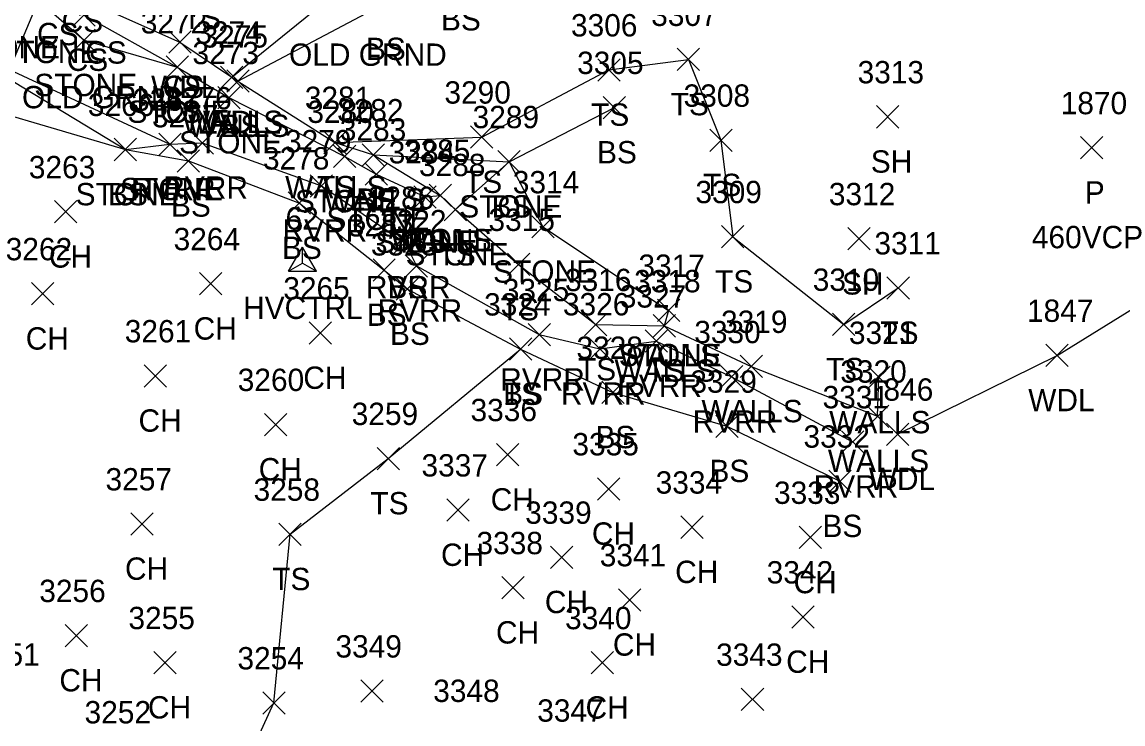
# Model space of a CAD drawing. Extents: x 462930 to 463548, y 29607 to 30453.
# Drawn here: x 463356.77 to 463386.81, y 30121.35 to 30140.5 of the extents above; entities that cross this region are included whole.
import ezdxf

# ---------------------------------------------------------------- set-up
doc = ezdxf.new("R2010")
doc.units = 0
for name, color, linetype in [('C_A', 7, 'Continuous'), ('C_I', 7, 'Continuous'), ('CPSM', 7, 'Continuous'), ('D_A', 7, 'Continuous'), ('D_C', 7, 'Continuous'), ('D_I', 7, 'Continuous'), ('D_TIC', 7, 'Continuous'), ('L_A', 7, 'Continuous'), ('L_C', 7, 'Continuous'), ('L_I', 7, 'Continuous'), ('L_TIC', 7, 'Continuous'), ('LASF', 7, 'Continuous'), ('LAWA', 7, 'Continuous'), ('LAWE', 7, 'Continuous'), ('LELB', 7, 'Continuous'), ('LWS', 7, 'Continuous'), ('UW', 7, 'Continuous')]:
    doc.layers.add(name, color=color, linetype=linetype)

msp = doc.modelspace()

# ---------------------------------------------------------------- linework, layer by layer
at = {"layer": 'CPSM'}
for p, q in [((463364.036, 30133.701), (463364.417, 30134.361)), ((463364.798, 30133.701), (463364.417, 30134.361)), ((463364.417, 30133.921), (463364.417, 30134.361)), ((463364.036, 30133.701), (463364.417, 30133.921)), ((463364.036, 30133.701), (463364.798, 30133.701)), ((463364.417, 30133.921), (463364.417, 30133.921)), ((463364.417, 30133.921), (463364.798, 30133.701))]:
    msp.add_line(p, q, dxfattribs=at)
at = {"layer": 'D_TIC'}
for points in [[(463385.651, 30136.765), (463386.261, 30137.375)], [(463386.261, 30136.765), (463385.651, 30137.375)]]:
    msp.add_lwpolyline(points, dxfattribs=at)
at = {"layer": 'L_TIC'}
for points in [[(463358.156, 30140.385), (463358.766, 30140.994)], [(463358.766, 30140.385), (463358.156, 30140.994)], [(463358.155, 30139.697), (463358.765, 30140.306)], [(463358.765, 30139.697), (463358.155, 30140.306)], [(463360.77, 30139.646), (463361.38, 30140.256)], [(463361.38, 30139.646), (463360.77, 30140.256)], [(463360.77, 30139.646), (463361.38, 30140.256)], [(463361.38, 30139.646), (463360.77, 30140.256)], [(463374.647, 30139.174), (463375.257, 30139.784)], [(463375.257, 30139.174), (463374.647, 30139.784)], [(463360.696, 30138.968), (463361.306, 30139.578)], [(463361.306, 30138.968), (463360.696, 30139.578)], [(463360.696, 30138.968), (463361.306, 30139.578)], [(463361.306, 30138.968), (463360.696, 30139.578)], [(463372.476, 30138.888), (463373.086, 30139.498)], [(463373.086, 30138.888), (463372.476, 30139.498)], [(463362.185, 30138.69), (463362.794, 30139.3)], [(463362.794, 30138.69), (463362.185, 30139.3)], [(463362.185, 30138.69), (463362.794, 30139.3)], [(463362.794, 30138.69), (463362.185, 30139.3)], [(463362.353, 30138.584), (463362.962, 30139.193)], [(463362.962, 30138.584), (463362.353, 30139.193)], [(463362.353, 30138.584), (463362.962, 30139.193)], [(463362.962, 30138.584), (463362.353, 30139.193)], [(463362.106, 30138.132), (463362.715, 30138.742)], [(463362.715, 30138.132), (463362.106, 30138.742)], [(463372.627, 30137.862), (463373.237, 30138.472)], [(463373.237, 30137.862), (463372.627, 30138.472)], [(463380.083, 30137.608), (463380.692, 30138.218)], [(463380.692, 30137.608), (463380.083, 30138.218)], [(463369.008, 30137.055), (463369.618, 30137.664)], [(463369.618, 30137.055), (463369.008, 30137.664)], [(463359.282, 30136.717), (463359.892, 30137.327)], [(463359.892, 30136.717), (463359.282, 30137.327)], [(463359.282, 30136.717), (463359.892, 30137.327)], [(463359.892, 30136.717), (463359.282, 30137.327)], [(463360.497, 30136.858), (463361.107, 30137.468)], [(463361.107, 30136.858), (463360.497, 30137.468)], [(463360.497, 30136.858), (463361.107, 30137.468)], [(463361.107, 30136.858), (463360.497, 30137.468)], [(463361.38, 30136.897), (463361.99, 30137.507)], [(463361.99, 30136.897), (463361.38, 30137.507)], [(463364.999, 30136.908), (463365.609, 30137.518)], [(463365.609, 30136.908), (463364.999, 30137.518)], [(463364.999, 30136.908), (463365.609, 30137.518)], [(463365.609, 30136.908), (463364.999, 30137.518)], [(463375.531, 30136.969), (463376.141, 30137.578)], [(463376.141, 30136.969), (463375.531, 30137.578)], [(463361.001, 30136.407), (463361.611, 30137.017)], [(463361.611, 30136.407), (463361.001, 30137.017)], [(463365.267, 30136.528), (463365.877, 30137.138)], [(463365.877, 30136.528), (463365.267, 30137.138)], [(463366.052, 30136.569), (463366.662, 30137.179)], [(463366.662, 30136.569), (463366.052, 30137.179)], [(463366.052, 30136.569), (463366.662, 30137.179)], [(463366.662, 30136.569), (463366.052, 30137.179)], [(463369.753, 30136.384), (463370.362, 30136.994)], [(463370.362, 30136.384), (463369.753, 30136.994)], [(463369.753, 30136.384), (463370.362, 30136.994)], [(463370.362, 30136.384), (463369.753, 30136.994)], [(463366.127, 30136.044), (463366.737, 30136.653)], [(463366.737, 30136.044), (463366.127, 30136.653)], [(463364.633, 30135.725), (463365.243, 30136.334)], [(463365.243, 30135.725), (463364.633, 30136.334)], [(463364.03, 30135.255), (463364.639, 30135.865)], [(463364.639, 30135.255), (463364.03, 30135.865)], [(463367.461, 30135.423), (463368.07, 30136.033)], [(463368.07, 30135.423), (463367.461, 30136.033)], [(463367.461, 30135.423), (463368.07, 30136.033)], [(463368.07, 30135.423), (463367.461, 30136.033)], [(463367.875, 30135.464), (463368.485, 30136.074)], [(463368.485, 30135.464), (463367.875, 30136.074)], [(463367.875, 30135.464), (463368.485, 30136.074)], [(463368.485, 30135.464), (463367.875, 30136.074)], [(463357.656, 30135.017), (463358.265, 30135.627)], [(463358.265, 30135.017), (463357.656, 30135.627)], [(463368.287, 30135.076), (463368.897, 30135.685)], [(463368.897, 30135.076), (463368.287, 30135.685)], [(463368.287, 30135.076), (463368.897, 30135.685)], [(463368.897, 30135.076), (463368.287, 30135.685)], [(463370.674, 30134.607), (463371.283, 30135.216)], [(463371.283, 30134.607), (463370.674, 30135.216)], [(463375.857, 30134.338), (463376.467, 30134.948)], [(463376.467, 30134.338), (463375.857, 30134.948)], [(463379.299, 30134.282), (463379.909, 30134.892)], [(463379.909, 30134.282), (463379.299, 30134.892)], [(463366.908, 30134.18), (463367.518, 30134.79)], [(463367.518, 30134.18), (463366.908, 30134.79)], [(463366.908, 30134.18), (463367.518, 30134.79)], [(463367.518, 30134.18), (463366.908, 30134.79)], [(463366.344, 30133.428), (463366.953, 30134.038)], [(463366.953, 30133.428), (463366.344, 30134.038)], [(463367.225, 30133.542), (463367.834, 30134.151)], [(463367.834, 30133.542), (463367.225, 30134.151)], [(463370.01, 30133.58), (463370.62, 30134.189)], [(463370.62, 30133.58), (463370.01, 30134.189)], [(463357.025, 30132.78), (463357.634, 30133.389)], [(463357.634, 30132.78), (463357.025, 30133.389)], [(463361.606, 30133.054), (463362.216, 30133.663)], [(463362.216, 30133.054), (463361.606, 30133.663)], [(463366.976, 30132.908), (463367.586, 30133.518)], [(463367.586, 30132.908), (463366.976, 30133.518)], [(463380.369, 30132.938), (463380.979, 30133.548)], [(463380.979, 30132.938), (463380.369, 30133.548)], [(463374.103, 30132.326), (463374.712, 30132.936)], [(463374.712, 30132.326), (463374.103, 30132.936)], [(463374.103, 30132.326), (463374.712, 30132.936)], [(463374.712, 30132.326), (463374.103, 30132.936)], [(463372.116, 30131.939), (463372.726, 30132.548)], [(463372.726, 30131.939), (463372.116, 30132.548)], [(463373.986, 30131.905), (463374.595, 30132.515)], [(463374.595, 30131.905), (463373.986, 30132.515)], [(463373.986, 30131.905), (463374.595, 30132.515)], [(463374.595, 30131.905), (463373.986, 30132.515)], [(463378.886, 30131.945), (463379.495, 30132.554)], [(463379.495, 30131.945), (463378.886, 30132.554)], [(463364.599, 30131.709), (463365.208, 30132.319)], [(463365.208, 30131.709), (463364.599, 30132.319)], [(463370.574, 30131.664), (463371.183, 30132.273)], [(463371.183, 30131.664), (463370.574, 30132.273)], [(463372.231, 30131.276), (463372.841, 30131.886)], [(463372.841, 30131.276), (463372.231, 30131.886)], [(463373.767, 30131.489), (463374.377, 30132.099)], [(463374.377, 30131.489), (463373.767, 30132.099)], [(463370.065, 30131.272), (463370.674, 30131.882)], [(463370.674, 30131.272), (463370.065, 30131.882)], [(463370.065, 30131.272), (463370.674, 30131.882)], [(463370.674, 30131.272), (463370.065, 30131.882)], [(463384.705, 30131.099), (463385.315, 30131.709)], [(463385.315, 30131.099), (463384.705, 30131.709)], [(463376.359, 30130.797), (463376.969, 30131.406)], [(463376.969, 30130.797), (463376.359, 30131.406)], [(463360.101, 30130.54), (463360.71, 30131.15)], [(463360.71, 30130.54), (463360.101, 30131.15)], [(463375.825, 30130.517), (463376.435, 30131.126)], [(463376.435, 30130.517), (463375.825, 30131.126)], [(463379.846, 30130.496), (463380.456, 30131.105)], [(463380.456, 30130.496), (463379.846, 30131.105)], [(463372.585, 30130.089), (463373.195, 30130.699)], [(463373.195, 30130.089), (463372.585, 30130.699)], [(463363.381, 30129.212), (463363.991, 30129.821)], [(463363.991, 30129.212), (463363.381, 30129.821)], [(463379.81, 30129.44), (463380.419, 30130.049)], [(463380.419, 30129.44), (463379.81, 30130.049)], [(463375.695, 30129.165), (463376.305, 30129.775)], [(463376.305, 30129.165), (463375.695, 30129.775)], [(463380.353, 30128.948), (463380.963, 30129.558)], [(463380.963, 30128.948), (463380.353, 30129.558)], [(463379.127, 30128.74), (463379.737, 30129.349)], [(463379.737, 30128.74), (463379.127, 30129.349)], [(463366.453, 30128.284), (463367.063, 30128.894)], [(463367.063, 30128.284), (463366.453, 30128.894)], [(463369.711, 30128.389), (463370.32, 30128.998)], [(463370.32, 30128.389), (463369.711, 30128.998)], [(463372.473, 30127.456), (463373.082, 30128.066)], [(463373.082, 30127.456), (463372.473, 30128.066)], [(463378.78, 30127.666), (463379.389, 30128.275)], [(463379.389, 30127.666), (463378.78, 30128.275)], [(463368.356, 30126.878), (463368.966, 30127.488)], [(463368.966, 30126.878), (463368.356, 30127.488)], [(463359.733, 30126.499), (463360.343, 30127.109)], [(463360.343, 30126.499), (463359.733, 30127.109)], [(463363.774, 30126.217), (463364.384, 30126.826)], [(463364.384, 30126.217), (463363.774, 30126.826)], [(463374.745, 30126.411), (463375.355, 30127.021)], [(463375.355, 30126.411), (463374.745, 30127.021)], [(463377.975, 30126.132), (463378.585, 30126.742)], [(463378.585, 30126.132), (463377.975, 30126.742)], [(463371.189, 30125.589), (463371.798, 30126.199)], [(463371.798, 30125.589), (463371.189, 30126.199)], [(463369.856, 30124.759), (463370.465, 30125.368)], [(463370.465, 30124.759), (463369.856, 30125.368)], [(463373.046, 30124.428), (463373.656, 30125.037)], [(463373.656, 30124.428), (463373.046, 30125.037)], [(463377.774, 30123.96), (463378.384, 30124.57)], [(463378.384, 30123.96), (463377.774, 30124.57)], [(463357.942, 30123.453), (463358.552, 30124.063)], [(463358.552, 30123.453), (463357.942, 30124.063)], [(463360.359, 30122.714), (463360.969, 30123.324)], [(463360.969, 30122.714), (463360.359, 30123.324)], [(463372.3, 30122.711), (463372.91, 30123.321)], [(463372.91, 30122.711), (463372.3, 30123.321)], [(463366.01, 30121.939), (463366.619, 30122.548)], [(463366.619, 30121.939), (463366.01, 30122.548)], [(463376.394, 30121.713), (463377.004, 30122.322)], [(463377.004, 30121.713), (463376.394, 30122.322)], [(463363.333, 30121.614), (463363.943, 30122.224)], [(463363.943, 30121.614), (463363.333, 30122.224)]]:
    msp.add_lwpolyline(points, dxfattribs=at)
at = {"layer": 'LASF'}
for points in [[(463335.666, 30151.825), (463334.307, 30149.365), (463333.551, 30148), (463337.382, 30145.968), (463341.269, 30144.863), (463346.266, 30143.58), (463350.176, 30142.23), (463354.589, 30140.054), (463359.587, 30137.022), (463360.802, 30137.163)], [(463335.666, 30151.825), (463339.994, 30150.186), (463344.731, 30148.092), (463345.991, 30147.14), (463346.905, 30145.251), (463349.408, 30144.305), (463351.788, 30143.206), (463354.335, 30142.295), (463356.35, 30141.031), (463357.426, 30140.903), (463358.46, 30140.002), (463361.001, 30139.273), (463362.41, 30138.437), (463365.572, 30136.833), (463366.432, 30136.349), (463367.765, 30135.728), (463368.18, 30135.769), (463368.592, 30135.381), (463370.057, 30136.689), (463370.978, 30134.911), (463374.408, 30132.631)]]:
    msp.add_lwpolyline(points, dxfattribs=at)
at = {"layer": 'LAWA'}
for points in [[(463380.658, 30129.253), (463385.01, 30131.404), (463390.048, 30134.524), (463393.052, 30140.479), (463397.05, 30150.402), (463401.541, 30159.789)], [(463361.075, 30139.951), (463362.489, 30138.995), (463366.254, 30142.049), (463368.112, 30145.132), (463368.96, 30147.708), (463370.031, 30148.832), (463372.15, 30149.242), (463373.697, 30150.393), (463375.482, 30151.895)]]:
    msp.add_lwpolyline(points, dxfattribs=at)
at = {"layer": 'LAWE'}
msp.add_lwpolyline([(463312.771, 30156.48), (463317.927, 30154.119), (463323.301, 30150.297), (463329.2, 30147.672), (463333.781, 30145.982), (463336.917, 30145.16), (463341.124, 30143.089), (463345.902, 30142.661), (463349.953, 30140.952), (463354.589, 30140.054), (463360.802, 30137.163), (463361.685, 30137.202), (463364.938, 30136.029), (463367.213, 30134.485), (463367.529, 30133.847), (463370.878, 30131.969), (463372.536, 30131.581), (463374.072, 30131.794), (463376.13, 30130.821), (463379.432, 30129.045)], dxfattribs=at)
at = {"layer": 'LELB'}
for points in [[(463311.51, 30154.564), (463317.305, 30152.12), (463328.108, 30145.648), (463332.48, 30143.532), (463335.24, 30142.565), (463339.678, 30141.183), (463343.544, 30141.846), (463345.752, 30141.37), (463349.534, 30139.719), (463354.026, 30138.661), (463359.587, 30137.022), (463361.306, 30136.712), (463364.334, 30135.56), (463366.649, 30133.733), (463367.281, 30133.213), (463370.369, 30131.577), (463372.89, 30130.394), (463376, 30129.47), (463379.084, 30127.97)], [(463362.657, 30138.888), (463366.626, 30140.987), (463368.673, 30141.794), (463369.614, 30144.668), (463372.764, 30146.82), (463375.23, 30148.304), (463377.492, 30152.624)], [(463338.725, 30147.014), (463341.902, 30146.288), (463346.905, 30145.251), (463349.39, 30146.891), (463350.92, 30147.048), (463352.297, 30147.355), (463353.139, 30145.924), (463354.358, 30144.307), (463355.85, 30144.681), (463357.539, 30144.184), (463357.985, 30144.223), (463357.945, 30143.102), (463357.652, 30141.391), (463358.461, 30140.69), (463361.001, 30139.273)], [(463357.985, 30144.223), (463358.976, 30143.588), (463358.67, 30142.627), (463358.321, 30141.75), (463358.966, 30140.889), (463361.075, 30139.951)], [(463365.304, 30137.213), (463369.313, 30137.36), (463372.781, 30139.193), (463374.952, 30139.479), (463375.836, 30137.274), (463376.162, 30134.643), (463379.19, 30132.249), (463380.674, 30133.243)], [(463366.357, 30136.874), (463370.057, 30136.689), (463372.932, 30138.167)], [(463367.765, 30135.728), (463367.213, 30134.485)], [(463368.592, 30135.381), (463370.315, 30133.884), (463372.421, 30132.243), (463374.291, 30132.21)], [(463357.518, 30115.65), (463362.332, 30119.061), (463363.638, 30121.919), (463364.079, 30126.521), (463366.758, 30128.589), (463370.369, 30131.577)]]:
    msp.add_lwpolyline(points, dxfattribs=at)
at = {"layer": 'LWS'}
for points in [[(463362.489, 30138.995), (463362.657, 30138.888), (463365.304, 30137.213), (463366.357, 30136.874), (463368.18, 30135.769)], [(463374.408, 30132.631), (463374.291, 30132.21), (463376.664, 30131.102), (463380.114, 30129.744), (463380.151, 30130.801)]]:
    msp.add_lwpolyline(points, dxfattribs=at)
at = {"layer": 'UW'}
msp.add_lwpolyline([(463344.573, 30111.096), (463359.121, 30145.596)], dxfattribs=at)

# ---------------------------------------------------------------- texts
at = {"layer": 'C_A'}
msp.add_text('HVCTRL', height=0.6096, dxfattribs=at).set_placement((463362.799, 30132.397))
at = {"layer": 'C_I'}
msp.add_text('62', height=0.6096, dxfattribs=at).set_placement((463363.956, 30134.835))
at = {"layer": 'D_A'}
msp.add_text('P', height=0.61, dxfattribs=at).set_placement((463385.766, 30135.546))
at = {"layer": 'D_C'}
msp.add_text('460VCP', height=0.6096, dxfattribs=at).set_placement((463384.322, 30134.327))
at = {"layer": 'D_I'}
msp.add_text('1870', height=0.6096, dxfattribs=at).set_placement((463385.109, 30137.984))
at = {"layer": 'L_A'}
for s, p in [('TS', (463361.158, 30140.307)), ('CS', (463357.846, 30140.226)), ('BS', (463368.198, 30140.27)), ('CS', (463357.176, 30139.867)), ('STONE', (463354.992, 30139.507)), ('STONE', (463356.068, 30139.379)), ('BS', (463366.151, 30139.463)), ('CS', (463357.986, 30139.166)), ('CS', (463358.491, 30139.365)), ('STONE', (463357.101, 30138.478)), ('WDL', (463360.288, 30138.427)), ('CS', (463360.6, 30138.427)), ('TS', (463374.467, 30137.955)), ('STONE', (463359.643, 30137.749)), ('CS', (463360.526, 30137.749)), ('TS', (463372.296, 30137.669)), ('WALLS', (463361.131, 30137.471)), ('WALLS', (463361.299, 30137.364)), ('WDL', (463361.702, 30137.471)), ('BS', (463362.182, 30137.364)), ('STONE', (463361.052, 30136.913)), ('BS', (463372.457, 30136.643)), ('SH', (463379.927, 30136.389)), ('TS', (463368.828, 30135.836)), ('STONE', (463358.229, 30135.498)), ('BS', (463359.112, 30135.498)), ('STONE', (463359.444, 30135.639)), ('RVRR', (463359.739, 30135.639)), ('RVRR', (463360.622, 30135.678)), ('WALLS', (463363.946, 30135.689)), ('TS', (463364.819, 30135.689)), ('TS', (463375.352, 30135.75)), ('BS', (463360.831, 30135.188)), ('STONE', (463364.214, 30135.309)), ('WALLS', (463364.999, 30135.35)), ('BS', (463365.882, 30135.35)), ('STONE', (463368.699, 30135.165)), ('BS', (463369.582, 30135.165)), ('STONE', (463365.073, 30134.825)), ('RVRR', (463363.875, 30134.505)), ('BS', (463363.859, 30134.036)), ('STONE', (463366.407, 30134.204)), ('WALLS', (463366.822, 30134.245)), ('STONE', (463366.822, 30134.245)), ('BS', (463367.29, 30134.204)), ('CH', (463357.5, 30133.798)), ('STONE', (463367.233, 30133.857)), ('TS', (463368.107, 30133.857)), ('STONE', (463369.62, 30133.387)), ('TS', (463375.677, 30133.119)), ('RVRR', (463366.15, 30132.961)), ('BS', (463366.738, 30132.961)), ('SH', (463379.143, 30133.063)), ('BS', (463366.173, 30132.209)), ('RVRR', (463366.466, 30132.323)), ('TS', (463369.83, 30132.36)), ('CH', (463361.45, 30131.834)), ('BS', (463366.806, 30131.689)), ('TS', (463380.189, 30131.719)), ('CH', (463356.869, 30131.561)), ('WALLS', (463373.049, 30131.107)), ('STONE', (463373.049, 30131.107)), ('TS', (463371.936, 30130.719)), ('WALLS', (463372.932, 30130.686)), ('TS', (463373.806, 30130.686)), ('TS', (463378.706, 30130.725)), ('CH', (463364.443, 30130.49)), ('RVRR', (463369.815, 30130.445)), ('RVRR', (463373.009, 30130.27)), ('TS', (463369.885, 30130.053)), ('BS', (463369.894, 30130.053)), ('RVRR', (463371.473, 30130.057)), ('WDL', (463384.223, 30129.88)), ('WALLS', (463375.306, 30129.578)), ('CH', (463359.945, 30129.321)), ('RVRR', (463375.067, 30129.297)), ('WALLS', (463378.792, 30129.277)), ('BS', (463372.415, 30128.87)), ('CH', (463363.225, 30127.993)), ('WALLS', (463378.756, 30128.22)), ('BS', (463375.525, 30127.946)), ('WDL', (463379.871, 30127.729)), ('RVRR', (463378.369, 30127.521)), ('TS', (463366.273, 30127.065)), ('CH', (463369.555, 30127.169)), ('CH', (463372.317, 30126.237)), ('BS', (463378.609, 30126.446)), ('CH', (463368.2, 30125.659)), ('CH', (463359.577, 30125.28)), ('TS', (463363.594, 30124.997)), ('CH', (463374.589, 30125.192)), ('CH', (463377.819, 30124.913)), ('CH', (463371.033, 30124.37)), ('CH', (463369.7, 30123.54)), ('CH', (463372.89, 30123.209)), ('CH', (463377.618, 30122.741)), ('CH', (463357.786, 30122.234)), ('CH', (463360.203, 30121.495)), ('CH', (463372.144, 30121.492))]:
    msp.add_text(s, height=0.6096, dxfattribs=at).set_placement(p)
at = {"layer": 'L_C'}
for p in [(463364.053, 30139.305), (463356.766, 30138.146)]:
    msp.add_text('OLD GRND', height=0.6096, dxfattribs=at).set_placement(p)
at = {"layer": 'L_I'}
for s, p in [('3307', (463373.935, 30140.393)), ('3272', (463360.007, 30140.188)), ('3272', (463360.007, 30140.188)), ('3306', (463371.746, 30140.107)), ('3274', (463361.496, 30139.909)), ('3274', (463361.496, 30139.909)), ('3275', (463361.664, 30139.803)), ('3275', (463361.664, 30139.803)), ('3273', (463361.417, 30139.351)), ('3305', (463371.914, 30139.082)), ('3313', (463379.567, 30138.827)), ('3290', (463368.293, 30138.274)), ('3308', (463374.819, 30138.188)), ('3266', (463358.562, 30137.936)), ('3266', (463358.562, 30137.936)), ('3267', (463359.794, 30138.077)), ('3267', (463359.794, 30138.077)), ('3276', (463360.675, 30138.116)), ('3281', (463364.483, 30138.127)), ('3281', (463364.483, 30138.127)), ('3277', (463360.312, 30137.626)), ('3280', (463364.552, 30137.747)), ('3282', (463365.364, 30137.788)), ('3282', (463365.364, 30137.788)), ('3289', (463369.061, 30137.603)), ('3289', (463369.061, 30137.603)), ('3283', (463365.438, 30137.263)), ('3279', (463363.942, 30136.944)), ('3285', (463367.186, 30136.684)), ('3285', (463367.186, 30136.684)), ('3278', (463363.341, 30136.475)), ('3284', (463366.772, 30136.642)), ('3284', (463366.772, 30136.642)), ('3263', (463356.952, 30136.236)), ('3288', (463367.598, 30136.295)), ('3288', (463367.598, 30136.295)), ('3314', (463370.158, 30135.826)), ('3309', (463375.142, 30135.557)), ('3312', (463378.783, 30135.501)), ('3286', (463366.202, 30135.399)), ('3286', (463366.202, 30135.399)), ('3287', (463365.655, 30134.648)), ('3322', (463366.536, 30134.761)), ('3315', (463369.494, 30134.799)), ('3264', (463360.903, 30134.273)), ('3262', (463356.321, 30133.999)), ('3323', (463366.287, 30134.128)), ('3311', (463380.026, 30134.158)), ('3317', (463373.587, 30133.546)), ('3317', (463373.587, 30133.546)), ('3316', (463371.583, 30133.158)), ('3318', (463373.47, 30133.125)), ('3318', (463373.47, 30133.125)), ('3310', (463378.343, 30133.164)), ('3265', (463363.896, 30132.929)), ('3325', (463369.885, 30132.883)), ('3324', (463369.376, 30132.491)), ('3324', (463369.376, 30132.491)), ('3326', (463371.526, 30132.495)), ('3327', (463373.078, 30132.708)), ('1847', (463384.189, 30132.318)), ('3319', (463375.841, 30132.016)), ('3261', (463359.57, 30131.759)), ('3330', (463375.11, 30131.736)), ('3321', (463379.33, 30131.715)), ('3328', (463371.896, 30131.308)), ('3260', (463362.652, 30130.431)), ('3329', (463375.004, 30130.384)), ('3320', (463379.094, 30130.659)), ('1846', (463379.82, 30130.167)), ('3331', (463378.611, 30129.959)), ('3259', (463365.762, 30129.503)), ('3336', (463369.005, 30129.608)), ('3332', (463378.091, 30128.885)), ('3335', (463371.784, 30128.675)), ('3337', (463367.667, 30128.098)), ('3257', (463359.045, 30127.718)), ('3258', (463363.085, 30127.436)), ('3334', (463374.056, 30127.631)), ('3333', (463377.286, 30127.351)), ('3339', (463370.497, 30126.808)), ('3338', (463369.167, 30125.978)), ('3341', (463372.53, 30125.647)), ('3342', (463377.086, 30125.179)), ('3256', (463357.237, 30124.672)), ('3255', (463359.67, 30123.933)), ('3340', (463371.585, 30123.931)), ('3349', (463365.319, 30123.158)), ('3251', (463355.436, 30122.936)), ('3343', (463375.706, 30122.932)), ('3254', (463362.645, 30122.834)), ('3348', (463367.987, 30121.946)), ('3252', (463358.473, 30121.361)), ('3347', (463370.825, 30121.408))]:
    msp.add_text(s, height=0.6096, dxfattribs=at).set_placement(p)

doc.saveas('drawing.dxf')
